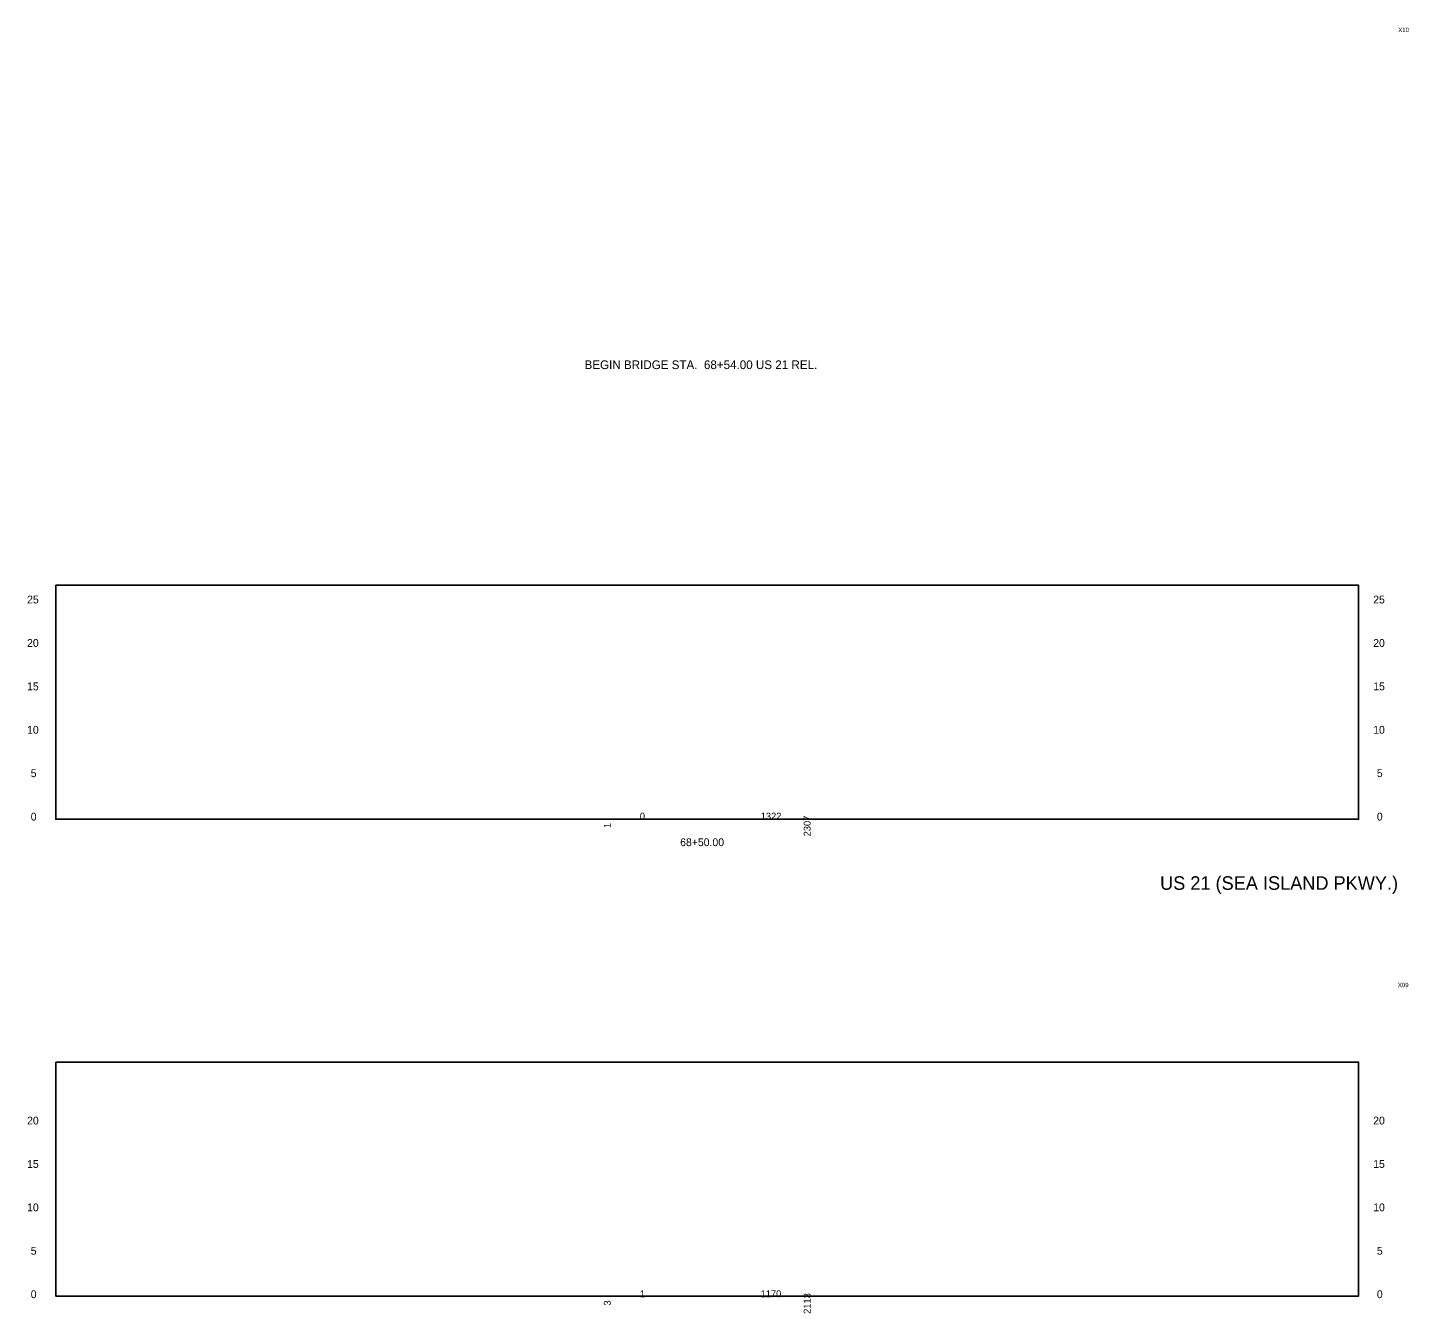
# Model space of a CAD drawing. Extents: x 971 to 1131, y 2203 to 6043.
# Drawn here: x 971.5 to 1130.5, y 3145.1 to 3293.2 of the extents above; entities that cross this region are included whole.
import ezdxf

# ---------------------------------------------------------------- set-up
doc = ezdxf.new("R2010")
doc.units = 0
for name, color, linetype in [('RD_SHT_Misc1', 7, 'Continuous'), ('RD_SHT_ShtClip', 7, 'Continuous'), ('RD_SHT_TX', 7, 'Continuous'), ('RD_TX_StaOff', 7, 'Continuous'), ('RD_XS_TX_Station', 7, 'Continuous')]:
    doc.layers.add(name, color=color, linetype=linetype)

msp = doc.modelspace()

# ---------------------------------------------------------------- linework, layer by layer
at = {"layer": 'RD_SHT_ShtClip'}
for points in [[(974.73, 3228.97), (1124.73, 3228.97), (1124.73, 3202.02), (974.73, 3202.02)], [(974.73, 3174.05), (1124.73, 3174.05), (1124.73, 3147.1), (974.73, 3147.1)]]:
    msp.add_lwpolyline(points, close=True, dxfattribs=at)

# ---------------------------------------------------------------- texts
at = {"layer": 'RD_SHT_Misc1'}
for s, rotation, p in [('0', 360, (1041.97, 3201.97)), ('2307', 90, (1061.64, 3200.05)), ('1', 90, (1038.63, 3201.01)), ('3', 90, (1038.63, 3146.02)), ('2113', 90, (1061.64, 3145.06))]:
    msp.add_text(s, height=0.8, rotation=rotation, dxfattribs=at).set_placement(p)
for s, p in [('1322', (1055.89, 3201.97)), ('1', (1041.98, 3146.97)), ('1170', (1055.88, 3146.97))]:
    msp.add_text(s, height=0.8, dxfattribs=at).set_placement(p)
at = {"layer": 'RD_SHT_TX'}
for s, p in [('X10', (1129.31, 3292.68)), ('X09', (1129.26, 3182.68))]:
    msp.add_text(s, height=0.5, rotation=360, dxfattribs=at).set_placement(p)
for s, height, p in [('25', 0.9, (971.42, 3226.87)), ('25', 0.9, (1126.42, 3226.87)), ('20', 0.9, (971.42, 3221.87)), ('20', 0.9, (1126.42, 3221.87)), ('15', 0.9, (971.42, 3216.87)), ('15', 0.9, (1126.42, 3216.87)), ('10', 0.9, (971.42, 3211.87)), ('10', 0.9, (1126.42, 3211.87)), ('5', 0.9, (971.84, 3206.87)), ('5', 0.9, (1126.84, 3206.87)), ('0', 0.9, (971.84, 3201.87)), ('0', 0.9, (1126.84, 3201.87)), ('US 21 (SEA ISLAND PKWY.)', 1.5625, (1101.88, 3193.89)), ('20', 0.9, (971.42, 3166.87)), ('20', 0.9, (1126.42, 3166.87)), ('15', 0.9, (971.42, 3161.87)), ('15', 0.9, (1126.42, 3161.87)), ('10', 0.9, (971.42, 3156.87)), ('10', 0.9, (1126.42, 3156.87)), ('5', 0.9, (971.84, 3151.87)), ('5', 0.9, (1126.84, 3151.87)), ('0', 0.9, (971.84, 3146.87)), ('0', 0.9, (1126.84, 3146.87))]:
    msp.add_text(s, height=height, dxfattribs=at).set_placement(p)
at = {"layer": 'RD_TX_StaOff'}
msp.add_text('BEGIN BRIDGE STA.  68+54.00 US 21 REL.', height=1, dxfattribs=at).set_placement((1035.61, 3253.86))
at = {"layer": 'RD_XS_TX_Station'}
msp.add_text('68+50.00', height=0.9, dxfattribs=at).set_placement((1046.62, 3198.92))

doc.saveas('drawing.dxf')
